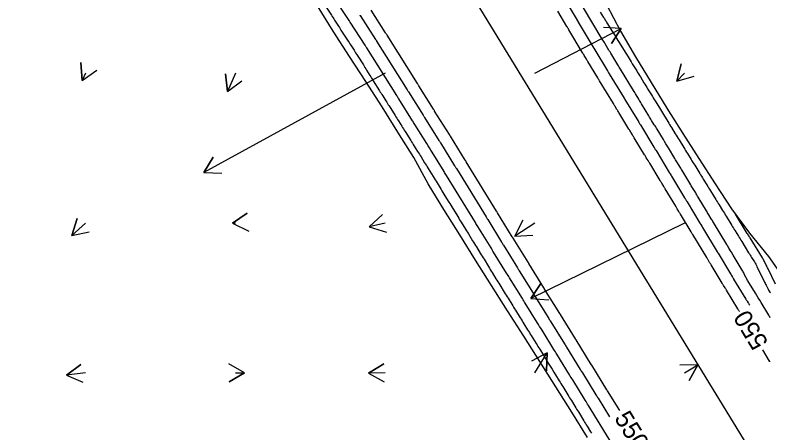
# Model space of a CAD drawing. Extents: x 954385 to 988206, y 1868364 to 1924553.
# Drawn here: x 956633.6 to 956885.7, y 1921348.9 to 1921488.4 of the extents above; entities that cross this region are included whole.
import ezdxf

# ---------------------------------------------------------------- set-up
doc = ezdxf.new("R2010")
doc.units = 0
for name, color, linetype in [('24', 7, 'Continuous'), ('26', 7, 'Continuous'), ('5', 7, 'Continuous'), ('6', 7, 'Continuous'), ('7', 7, 'Continuous'), ('Default', 7, 'Continuous')]:
    doc.layers.add(name, color=color, linetype=linetype)

msp = doc.modelspace()

# ---------------------------------------------------------------- linework, layer by layer
at = {"layer": '24'}
for points in [[(956824.81, 1921347.37), (956819.48, 1921355.83), (956814.15, 1921364.29), (956808.81, 1921372.75), (956803.45, 1921381.19), (956798.08, 1921389.63), (956792.73, 1921398.08), (956787.39, 1921406.53), (956782.08, 1921415.01), (956776.8, 1921423.5), (956771.5, 1921431.98), (956766.73, 1921440.79), (956761.4, 1921449.25), (956756.18, 1921457.78), (956750.7, 1921466.15), (956745.31, 1921474.58), (956739.85, 1921482.96), (956734.55, 1921491.44)], [(956831.07, 1921491.88), (956835.81, 1921483.05), (956840.83, 1921474.4), (956846.08, 1921465.89), (956851.23, 1921457.32), (956856.61, 1921448.89), (956861.99, 1921440.46), (956867.43, 1921432.06), (956872.87, 1921423.67), (956878.85, 1921415.6), (956885.2, 1921407.77), (956890.96, 1921399.57)]]:
    msp.add_lwpolyline(points, dxfattribs=at)
at = {"layer": '26'}
for points in [[(956807.13, 1921468.93), (956836.05, 1921483.93), (956832.82, 1921478.87), (956836.05, 1921483.93), (956830.06, 1921484.2)], [(956657.13, 1921468.93), (956656, 1921466.52), (956655.5, 1921472.5), (956656, 1921466.52), (956660.92, 1921469.95)], [(956857.13, 1921468.93), (956854.6, 1921466.31), (956856.05, 1921472.13), (956854.6, 1921466.31), (956860.36, 1921467.96)], [(956757.13, 1921468.93), (956696.62, 1921435.77), (956699.73, 1921440.9), (956696.62, 1921435.77), (956702.61, 1921435.64)], [(956707.13, 1921468.93), (956704.51, 1921462.81), (956703.8, 1921468.76), (956704.51, 1921462.81), (956709.31, 1921466.4)], [(956657.13, 1921418.93), (956652.49, 1921414.76), (956654.35, 1921420.46), (956652.49, 1921414.76), (956658.36, 1921416)], [(956707.13, 1921418.93), (956706.18, 1921418.85), (956711.12, 1921422.26), (956706.18, 1921418.85), (956711.59, 1921416.27)], [(956757.13, 1921418.93), (956751.85, 1921417.72), (956756.24, 1921421.8), (956751.85, 1921417.72), (956757.58, 1921415.95)], [(956807.13, 1921418.93), (956800.46, 1921414.56), (956803.16, 1921419.92), (956800.46, 1921414.56), (956806.45, 1921414.9)], [(956857.13, 1921418.93), (956805.87, 1921393.76), (956809.22, 1921398.74), (956805.87, 1921393.76), (956811.86, 1921393.36)], [(956807.13, 1921368.93), (956811.33, 1921375.6), (956811.1, 1921369.6), (956811.33, 1921375.6), (956806.02, 1921372.8)], [(956657.13, 1921368.93), (956650.7, 1921368.15), (956655.5, 1921371.75), (956650.7, 1921368.15), (956656.22, 1921365.8)], [(956707.13, 1921368.93), (956710.18, 1921368.98), (956705.04, 1921365.89), (956710.18, 1921368.98), (956704.94, 1921371.89)], [(956757.13, 1921368.93), (956751.58, 1921368.84), (956756.73, 1921371.92), (956751.58, 1921368.84), (956756.83, 1921365.92)], [(956857.13, 1921368.93), (956861.65, 1921371.57), (956858.68, 1921366.36), (956861.65, 1921371.57), (956855.65, 1921371.54)]]:
    msp.add_lwpolyline(points, dxfattribs=at)
at = {"layer": '6'}
for points in [[(956835.53, 1921356.32), (956831.44, 1921362.96), (956831.36, 1921363.1), (956831.27, 1921363.23), (956826.2, 1921371.47), (956826.15, 1921371.54), (956826.11, 1921371.61), (956826.07, 1921371.68), (956826.02, 1921371.75), (956820.95, 1921379.96), (956820.9, 1921380.03), (956820.85, 1921380.11), (956820.8, 1921380.19), (956820.75, 1921380.27), (956815.69, 1921388.44), (956815.64, 1921388.53), (956815.59, 1921388.62), (956815.53, 1921388.71), (956815.48, 1921388.79), (956810.43, 1921396.91), (956810.37, 1921397.01), (956810.31, 1921397.11), (956810.25, 1921397.21), (956810.19, 1921397.31), (956805.18, 1921405.4), (956805.11, 1921405.5), (956805.04, 1921405.61), (956804.98, 1921405.72), (956804.91, 1921405.83), (956799.94, 1921413.89), (956799.87, 1921414.01), (956799.8, 1921414.13), (956799.72, 1921414.24), (956799.65, 1921414.36), (956794.7, 1921422.4), (956794.63, 1921422.52), (956794.56, 1921422.64), (956794.48, 1921422.76), (956794.41, 1921422.88), (956784.24, 1921439.43), (956784.16, 1921439.55), (956784.08, 1921439.68), (956784, 1921439.81), (956783.93, 1921439.94), (956778.99, 1921447.92), (956778.91, 1921448.05), (956778.83, 1921448.19), (956778.74, 1921448.32), (956778.66, 1921448.46), (956773.7, 1921456.35), (956773.6, 1921456.51), (956773.51, 1921456.66), (956773.41, 1921456.81), (956773.32, 1921456.96), (956768.41, 1921464.79), (956768.3, 1921464.96), (956768.19, 1921465.13), (956768.09, 1921465.3), (956767.98, 1921465.48), (956757.82, 1921481.64), (956757.69, 1921481.86), (956757.56, 1921482.07), (956757.42, 1921482.28), (956757.28, 1921482.49), (956752.45, 1921489.97)], [(956875.51, 1921389.39), (956875.41, 1921389.55), (956875.3, 1921389.73), (956875.19, 1921389.91), (956875.07, 1921390.1), (956874.96, 1921390.28), (956871.15, 1921396.56), (956871.04, 1921396.75), (956870.92, 1921396.94), (956870.8, 1921397.13), (956870.69, 1921397.32), (956870.23, 1921398.08), (956870.11, 1921398.27), (956869.99, 1921398.46), (956869.88, 1921398.65), (956869.76, 1921398.84), (956866.02, 1921405.03), (956865.9, 1921405.23), (956865.78, 1921405.43), (956865.66, 1921405.62), (956865.54, 1921405.82), (956865.06, 1921406.62), (956864.94, 1921406.82), (956864.82, 1921407.02), (956864.7, 1921407.21), (956864.57, 1921407.41), (956859.89, 1921415.16), (956859.77, 1921415.36), (956859.64, 1921415.57), (956859.52, 1921415.78), (956859.39, 1921415.99), (956855.8, 1921421.94), (956855.67, 1921422.16), (956855.54, 1921422.38), (956855.4, 1921422.6), (956855.27, 1921422.82), (956854.74, 1921423.7), (956854.61, 1921423.92), (956854.48, 1921424.14), (956854.34, 1921424.36), (956854.21, 1921424.58), (956850.7, 1921430.4), (956850.56, 1921430.63), (956850.42, 1921430.86), (956850.28, 1921431.09), (956850.14, 1921431.32), (956849.58, 1921432.24), (956849.44, 1921432.47), (956849.3, 1921432.7), (956849.17, 1921432.93), (956849.03, 1921433.15), (956845.55, 1921438.88), (956845.41, 1921439.11), (956845.27, 1921439.35), (956845.12, 1921439.59), (956844.98, 1921439.82), (956844.4, 1921440.77), (956844.26, 1921441.01), (956844.12, 1921441.24), (956843.97, 1921441.48), (956843.83, 1921441.72), (956840.39, 1921447.37), (956840.24, 1921447.61), (956840.1, 1921447.85), (956839.95, 1921448.09), (956839.8, 1921448.34), (956839.21, 1921449.3), (956839.07, 1921449.55), (956838.92, 1921449.79), (956838.77, 1921450.03), (956838.62, 1921450.27), (956835.21, 1921455.87), (956835.06, 1921456.12), (956834.91, 1921456.36), (956834.76, 1921456.61), (956834.61, 1921456.86), (956834.02, 1921457.84), (956833.87, 1921458.08), (956833.72, 1921458.33), (956833.57, 1921458.57), (956833.42, 1921458.82), (956828.82, 1921466.37), (956828.67, 1921466.62), (956828.52, 1921466.87), (956828.36, 1921467.12), (956828.21, 1921467.37), (956824.89, 1921472.86), (956824.73, 1921473.11), (956824.58, 1921473.37), (956824.42, 1921473.63), (956824.26, 1921473.88), (956823.64, 1921474.91), (956823.49, 1921475.16), (956823.33, 1921475.42), (956823.18, 1921475.68), (956823.02, 1921475.94), (956818.54, 1921483.46), (956818.38, 1921483.74), (956818.21, 1921484.01), (956818.05, 1921484.29), (956817.88, 1921484.56), (956814.85, 1921489.64)], [(956885.69, 1921372.64), (956885.61, 1921372.78), (956885.58, 1921372.83), (956885.55, 1921372.87), (956883.3, 1921376.57)]]:
    msp.add_lwpolyline(points, dxfattribs=at)
at = {"layer": '7'}
for points in [[(956811.4, 1921503.25), (956821.3, 1921486.65), (956821.36, 1921486.54), (956821.43, 1921486.43), (956821.59, 1921486.15), (956821.66, 1921486.04), (956821.69, 1921485.99), (956826.65, 1921477.66), (956826.7, 1921477.58), (956826.74, 1921477.51), (956826.79, 1921477.43), (956826.83, 1921477.36), (956831.42, 1921469.79), (956831.52, 1921469.63), (956831.62, 1921469.46), (956831.83, 1921469.12), (956831.88, 1921469.04), (956831.93, 1921468.96), (956831.98, 1921468.87), (956832.03, 1921468.79), (956837.02, 1921460.59), (956837.08, 1921460.5), (956837.13, 1921460.42), (956837.18, 1921460.33), (956837.24, 1921460.24), (956841.77, 1921452.79), (956841.82, 1921452.7), (956841.88, 1921452.61), (956841.94, 1921452.52), (956841.99, 1921452.43), (956842.27, 1921451.97), (956842.44, 1921451.69), (956846.95, 1921444.29), (956847.01, 1921444.19), (956847.07, 1921444.1), (956847.12, 1921444), (956847.18, 1921443.91), (956847.41, 1921443.52), (956847.47, 1921443.43), (956847.53, 1921443.33), (956847.59, 1921443.24), (956847.65, 1921443.14), (956852.09, 1921435.81), (956852.15, 1921435.71), (956852.22, 1921435.6), (956852.28, 1921435.5), (956852.34, 1921435.4), (956852.59, 1921434.99), (956852.65, 1921434.89), (956852.72, 1921434.78), (956852.78, 1921434.68), (956852.84, 1921434.58), (956857.21, 1921427.35), (956857.28, 1921427.23), (956857.35, 1921427.12), (956857.42, 1921427.01), (956857.48, 1921426.9), (956857.75, 1921426.45), (956857.82, 1921426.34), (956857.89, 1921426.23), (956857.96, 1921426.11), (956858.03, 1921426), (956862.3, 1921418.9), (956862.38, 1921418.78), (956862.45, 1921418.65), (956862.53, 1921418.53), (956862.6, 1921418.41), (956862.9, 1921417.91), (956862.98, 1921417.78), (956863.05, 1921417.66), (956863.13, 1921417.54), (956863.2, 1921417.41), (956868.06, 1921409.37), (956868.15, 1921409.24), (956868.23, 1921409.1), (956868.31, 1921408.97), (956868.39, 1921408.84), (956872.54, 1921401.97), (956872.71, 1921401.69), (956872.89, 1921401.4), (956873.23, 1921400.83), (956873.32, 1921400.69), (956873.4, 1921400.55), (956873.49, 1921400.41), (956873.58, 1921400.26), (956877.7, 1921393.48), (956877.79, 1921393.34), (956877.88, 1921393.19), (956877.97, 1921393.04), (956878.06, 1921392.89), (956878.42, 1921392.3), (956878.51, 1921392.15), (956878.6, 1921392), (956878.69, 1921391.85), (956878.78, 1921391.71), (956878.93, 1921391.47)], [(956835, 1921341.92), (956825.07, 1921358.05), (956824.8, 1921358.48), (956824.53, 1921358.92), (956824.26, 1921359.36), (956823.99, 1921359.79), (956819.81, 1921366.58), (956819.55, 1921367.01), (956819.29, 1921367.43), (956819.02, 1921367.86), (956818.76, 1921368.29), (956814.53, 1921375.13), (956814.28, 1921375.53), (956814.03, 1921375.94), (956813.77, 1921376.35), (956813.52, 1921376.75), (956809.57, 1921383.13), (956809.17, 1921383.79), (956808.76, 1921384.44), (956808.35, 1921385.1), (956807.95, 1921385.75), (956803.97, 1921392.17), (956803.73, 1921392.55), (956803.49, 1921392.94), (956803.25, 1921393.33), (956803.01, 1921393.71), (956798.68, 1921400.7), (956798.45, 1921401.07), (956798.22, 1921401.44), (956797.99, 1921401.81), (956797.76, 1921402.18), (956793.41, 1921409.23), (956793.19, 1921409.59), (956792.97, 1921409.95), (956792.75, 1921410.31), (956792.53, 1921410.67), (956788.17, 1921417.76), (956787.95, 1921418.12), (956787.73, 1921418.47), (956787.51, 1921418.82), (956787.3, 1921419.17), (956777.67, 1921434.83), (956777.47, 1921435.17), (956777.26, 1921435.51), (956777.05, 1921435.84), (956776.84, 1921436.18), (956772.9, 1921442.56), (956772.45, 1921443.29), (956772, 1921444.01), (956771.55, 1921444.74), (956771.09, 1921445.46), (956767.07, 1921451.88), (956766.87, 1921452.18), (956766.68, 1921452.48), (956766.49, 1921452.79), (956766.3, 1921453.09), (956761.71, 1921460.41), (956761.54, 1921460.68), (956761.37, 1921460.96), (956761.2, 1921461.23), (956761.03, 1921461.5), (956751, 1921477.47), (956750.87, 1921477.68), (956750.73, 1921477.89), (956750.6, 1921478.1), (956750.46, 1921478.31), (956745.49, 1921486), (956745.4, 1921486.15), (956745.3, 1921486.29), (956745.21, 1921486.44), (956745.11, 1921486.59), (956739.97, 1921494.54)], [(956737.28, 1921491.33), (956739.23, 1921488.31), (956739.5, 1921487.9), (956739.77, 1921487.49), (956740.03, 1921487.08), (956740.3, 1921486.67), (956741.36, 1921485.03), (956741.63, 1921484.62), (956741.89, 1921484.21), (956742.16, 1921483.8), (956742.42, 1921483.39), (956744.58, 1921480.05), (956744.85, 1921479.62), (956745.13, 1921479.2), (956745.4, 1921478.78), (956745.68, 1921478.35), (956746.77, 1921476.66), (956747.05, 1921476.23), (956747.32, 1921475.81), (956747.59, 1921475.38), (956747.86, 1921474.95), (956749.89, 1921471.71), (956750.17, 1921471.27), (956750.44, 1921470.83), (956750.72, 1921470.4), (956750.99, 1921469.96), (956752.09, 1921468.21), (956752.36, 1921467.77), (956752.64, 1921467.34), (956752.91, 1921466.9), (956753.19, 1921466.46), (956755.29, 1921463.12), (956755.55, 1921462.69), (956755.82, 1921462.27), (956756.09, 1921461.84), (956756.36, 1921461.42), (956757.42, 1921459.72), (956757.69, 1921459.29), (956757.96, 1921458.87), (956758.22, 1921458.44), (956758.49, 1921458.02), (956760.47, 1921454.87), (956760.75, 1921454.42), (956761.03, 1921453.98), (956761.31, 1921453.53), (956761.59, 1921453.08), (956762.71, 1921451.29), (956762.99, 1921450.84), (956763.27, 1921450.4), (956763.55, 1921449.95), (956763.83, 1921449.5), (956765.73, 1921446.49), (956766.01, 1921446.03), (956766.3, 1921445.58), (956766.58, 1921445.12), (956766.87, 1921444.66), (956768.02, 1921442.84), (956768.3, 1921442.38), (956768.59, 1921441.93), (956768.87, 1921441.47), (956769.16, 1921441.01), (956770.34, 1921439.09), (956770.64, 1921438.61), (956770.93, 1921438.14), (956771.22, 1921437.67), (956771.51, 1921437.19), (956773.18, 1921434.49), (956773.52, 1921433.95), (956773.85, 1921433.42), (956774.18, 1921432.88), (956774.51, 1921432.35), (956775.84, 1921430.18), (956776.16, 1921429.65), (956776.49, 1921429.12), (956776.81, 1921428.6), (956777.13, 1921428.07), (956778.43, 1921425.96), (956778.76, 1921425.43), (956779.08, 1921424.9), (956779.41, 1921424.37), (956779.73, 1921423.84), (956781.1, 1921421.63), (956781.42, 1921421.1), (956781.74, 1921420.58), (956782.06, 1921420.05), (956782.39, 1921419.53), (956783.68, 1921417.43), (956784, 1921416.91), (956784.32, 1921416.38), (956784.64, 1921415.86), (956784.97, 1921415.33), (956786.37, 1921413.04), (956786.69, 1921412.53), (956787.01, 1921412.01), (956787.33, 1921411.49), (956787.65, 1921410.97), (956788.92, 1921408.9), (956789.24, 1921408.38), (956789.56, 1921407.86), (956789.88, 1921407.34), (956790.2, 1921406.83), (956791.67, 1921404.44), (956791.98, 1921403.93), (956792.3, 1921403.42), (956792.61, 1921402.92), (956792.93, 1921402.41), (956794.18, 1921400.37), (956794.5, 1921399.86), (956794.81, 1921399.35), (956795.12, 1921398.84), (956795.44, 1921398.34), (956796.98, 1921395.86), (956797.29, 1921395.36), (956797.6, 1921394.86), (956797.91, 1921394.35), (956798.22, 1921393.85), (956799.46, 1921391.85), (956799.77, 1921391.35), (956800.08, 1921390.85), (956800.39, 1921390.35), (956800.7, 1921389.85), (956802.29, 1921387.29), (956802.59, 1921386.8), (956802.9, 1921386.3), (956803.21, 1921385.81), (956803.51, 1921385.31), (956804.74, 1921383.34), (956805.04, 1921382.85), (956805.35, 1921382.35), (956805.66, 1921381.86), (956805.96, 1921381.37), (956807.6, 1921378.72), (956807.9, 1921378.24), (956808.2, 1921377.75), (956808.5, 1921377.26), (956808.8, 1921376.78), (956810.01, 1921374.83), (956810.31, 1921374.34), (956810.61, 1921373.85), (956810.91, 1921373.36), (956811.22, 1921372.88), (956812.91, 1921370.14), (956813.5, 1921369.18), (956814.09, 1921368.22), (956815.28, 1921366.31), (956815.58, 1921365.83), (956815.87, 1921365.35), (956816.17, 1921364.87), (956816.47, 1921364.39), (956818.21, 1921361.55), (956818.5, 1921361.08), (956818.79, 1921360.61), (956819.08, 1921360.14), (956819.37, 1921359.66), (956820.54, 1921357.78), (956820.83, 1921357.3), (956821.12, 1921356.83), (956821.41, 1921356.36), (956821.7, 1921355.89), (956823.52, 1921352.93), (956823.81, 1921352.47), (956824.09, 1921352.01), (956824.37, 1921351.55), (956824.66, 1921351.09), (956825.79, 1921349.24), (956826.08, 1921348.78)], [(956885.82, 1921387.34), (956885.66, 1921387.61), (956885.49, 1921387.89), (956885.32, 1921388.16), (956882.75, 1921392.4), (956882.27, 1921393.18), (956881.79, 1921393.96), (956881.32, 1921394.74), (956880.84, 1921395.52), (956878.34, 1921399.63), (956878.17, 1921399.92), (956878.01, 1921400.21), (956877.85, 1921400.51), (956877.7, 1921400.81), (956877.11, 1921402.03), (956876.96, 1921402.33), (956876.8, 1921402.63), (956876.64, 1921402.92), (956876.47, 1921403.21), (956873.46, 1921408.18), (956873.28, 1921408.48), (956873.1, 1921408.78), (956872.92, 1921409.08), (956872.73, 1921409.38), (956872, 1921410.59), (956871.82, 1921410.89), (956871.64, 1921411.19), (956871.46, 1921411.49), (956871.27, 1921411.79), (956866.86, 1921419.1), (956866.66, 1921419.42), (956866.46, 1921419.75), (956866.27, 1921420.07), (956866.07, 1921420.4), (956865.29, 1921421.7), (956865.09, 1921422.03), (956864.89, 1921422.35), (956864.7, 1921422.68), (956864.5, 1921423.01), (956861.71, 1921427.63), (956861.51, 1921427.97), (956861.3, 1921428.31), (956861.09, 1921428.65), (956860.89, 1921429), (956860.06, 1921430.37), (956859.85, 1921430.71), (956859.64, 1921431.05), (956859.44, 1921431.39), (956859.23, 1921431.74), (956856.56, 1921436.16), (956856.34, 1921436.51), (956856.13, 1921436.87), (956855.91, 1921437.23), (956855.7, 1921437.58), (956854.83, 1921439.01), (956854.61, 1921439.37), (956854.4, 1921439.72), (956854.18, 1921440.08), (956853.97, 1921440.44), (956851.79, 1921444.02), (956851.37, 1921444.72), (956850.94, 1921445.42), (956850.52, 1921446.12), (956850.09, 1921446.82), (956847.98, 1921450.29), (956847.76, 1921450.66), (956847.53, 1921451.02), (956847.31, 1921451.39), (956847.08, 1921451.76), (956846.19, 1921453.23), (956845.97, 1921453.59), (956845.74, 1921453.96), (956845.52, 1921454.33), (956845.29, 1921454.7), (956842.81, 1921458.77), (956842.58, 1921459.15), (956842.36, 1921459.52), (956842.13, 1921459.89), (956841.9, 1921460.27), (956840.99, 1921461.76), (956840.77, 1921462.13), (956840.54, 1921462.5), (956840.31, 1921462.88), (956840.09, 1921463.25), (956835.8, 1921470.29), (956835.57, 1921470.66), (956835.34, 1921471.04), (956835.11, 1921471.42), (956834.88, 1921471.8), (956832.51, 1921475.7), (956832.28, 1921476.09), (956832.04, 1921476.48), (956831.81, 1921476.87), (956831.57, 1921477.26), (956830.63, 1921478.82), (956830.39, 1921479.21), (956830.16, 1921479.6), (956829.92, 1921479.99), (956829.69, 1921480.38), (956823.46, 1921490.83)], [(956748.71, 1921488.38), (956748.77, 1921488.29), (956748.83, 1921488.21), (956753.98, 1921480.24), (956754.06, 1921480.11), (956754.14, 1921479.98), (956754.23, 1921479.85), (956754.31, 1921479.72), (956764.56, 1921463.39), (956764.67, 1921463.22), (956764.78, 1921463.04), (956764.89, 1921462.87), (956765, 1921462.7), (956769.85, 1921454.96), (956769.97, 1921454.76), (956770.1, 1921454.57), (956770.22, 1921454.38), (956770.34, 1921454.18), (956775.15, 1921446.53), (956775.28, 1921446.32), (956775.41, 1921446.1), (956775.55, 1921445.89), (956775.68, 1921445.67), (956780.39, 1921438.04), (956780.53, 1921437.82), (956780.67, 1921437.59), (956780.81, 1921437.37), (956780.95, 1921437.15), (956790.86, 1921421.02), (956791, 1921420.79), (956791.14, 1921420.56), (956791.29, 1921420.32), (956791.43, 1921420.09), (956796.09, 1921412.51), (956796.24, 1921412.28), (956796.38, 1921412.04), (956796.53, 1921411.8), (956796.67, 1921411.56), (956801.33, 1921404.01), (956801.48, 1921403.77), (956801.63, 1921403.53), (956801.78, 1921403.28), (956801.93, 1921403.04), (956806.59, 1921395.53), (956806.74, 1921395.28), (956806.9, 1921395.03), (956807.06, 1921394.78), (956807.21, 1921394.52), (956811.85, 1921387.05), (956812.01, 1921386.79), (956812.17, 1921386.53), (956812.34, 1921386.27), (956812.5, 1921386.01), (956817.1, 1921378.57), (956817.27, 1921378.3), (956817.44, 1921378.03), (956817.61, 1921377.75), (956817.77, 1921377.48), (956822.35, 1921370.08), (956822.52, 1921369.8), (956822.7, 1921369.52), (956822.87, 1921369.24), (956823.04, 1921368.96), (956827.59, 1921361.58), (956827.77, 1921361.3), (956827.94, 1921361.01), (956828.12, 1921360.72), (956828.3, 1921360.43), (956832.12, 1921354.22)], [(956829.03, 1921489.4), (956830.14, 1921487.62), (956830.42, 1921487.18), (956830.69, 1921486.73), (956830.97, 1921486.29), (956831.25, 1921485.84), (956833.16, 1921482.78), (956833.46, 1921482.29), (956833.77, 1921481.8), (956834.07, 1921481.32), (956834.37, 1921480.83), (956835.88, 1921478.38), (956836.79, 1921476.9), (956838.31, 1921474.43), (956838.66, 1921473.86), (956839.01, 1921473.29), (956839.36, 1921472.72), (956839.71, 1921472.15), (956841.19, 1921469.74), (956841.5, 1921469.24), (956841.8, 1921468.74), (956842.11, 1921468.25), (956842.41, 1921467.75), (956843.63, 1921465.76), (956843.94, 1921465.27), (956844.24, 1921464.77), (956844.55, 1921464.27), (956844.85, 1921463.78), (956846.11, 1921461.73), (956846.42, 1921461.22), (956846.73, 1921460.72), (956847.04, 1921460.21), (956847.35, 1921459.7), (956848.8, 1921457.36), (956849.14, 1921456.8), (956849.48, 1921456.25), (956849.82, 1921455.69), (956850.16, 1921455.14), (956851.57, 1921452.84), (956851.89, 1921452.33), (956852.2, 1921451.82), (956852.51, 1921451.3), (956852.83, 1921450.79), (956854.08, 1921448.75), (956854.4, 1921448.24), (956854.71, 1921447.73), (956855.03, 1921447.22), (956855.34, 1921446.7), (956856.92, 1921444.14), (956857.22, 1921443.64), (956857.53, 1921443.15), (956857.83, 1921442.66), (956858.13, 1921442.17), (956859.35, 1921440.2), (956859.65, 1921439.7), (956859.95, 1921439.21), (956860.26, 1921438.72), (956860.56, 1921438.23), (956862.25, 1921435.5), (956862.54, 1921435.02), (956862.84, 1921434.54), (956863.13, 1921434.06), (956863.43, 1921433.58), (956864.62, 1921431.66), (956864.91, 1921431.18), (956865.21, 1921430.7), (956865.51, 1921430.22), (956865.8, 1921429.74), (956867.6, 1921426.83), (956867.89, 1921426.37), (956868.18, 1921425.91), (956868.46, 1921425.44), (956868.75, 1921424.98), (956869.9, 1921423.13), (956870.18, 1921422.66), (956870.47, 1921422.2), (956870.76, 1921421.73), (956871.04, 1921421.27), (956872.96, 1921418.17), (956873.23, 1921417.72), (956873.51, 1921417.28), (956873.79, 1921416.83), (956874.06, 1921416.38), (956875.17, 1921414.59), (956875.45, 1921414.14), (956875.72, 1921413.69), (956876, 1921413.24), (956876.28, 1921412.79), (956878.59, 1921409.04), (956878.83, 1921408.65), (956879.07, 1921408.27), (956879.31, 1921407.88), (956879.54, 1921407.49), (956880.5, 1921405.95), (956880.73, 1921405.56), (956880.95, 1921405.17), (956881.17, 1921404.77), (956881.37, 1921404.36), (956883.75, 1921399.56), (956883.92, 1921399.22), (956884.09, 1921398.88), (956884.26, 1921398.55), (956884.42, 1921398.21), (956885.09, 1921396.86), (956885.27, 1921396.53), (956885.47, 1921396.21), (956885.68, 1921395.9), (956885.92, 1921395.61)], [(956887.57, 1921398.59), (956885.07, 1921403.64), (956884.92, 1921403.95), (956884.76, 1921404.26), (956884.61, 1921404.57), (956884.45, 1921404.88), (956883.84, 1921406.12), (956883.68, 1921406.43), (956883.52, 1921406.74), (956883.35, 1921407.04), (956883.17, 1921407.33), (956879.04, 1921414.02), (956878.89, 1921414.27), (956878.74, 1921414.52), (956878.43, 1921415.01), (956878.36, 1921415.13), (956878.28, 1921415.26), (956878.21, 1921415.38), (956878.13, 1921415.5), (956874.16, 1921421.93)]]:
    msp.add_lwpolyline(points, dxfattribs=at)
at = {"layer": 'Default'}
msp.add_line((957221.14, 1920784.24), (956045.8, 1922705.18), dxfattribs=at)

# ---------------------------------------------------------------- texts
at = {"layer": '5'}
for rotation, p in [(121.2999, (956885.31, 1921379.05)), (301.5643, (956833.53, 1921353.83))]:
    msp.add_text('550', height=6, rotation=rotation, dxfattribs=at).set_placement(p)

doc.saveas('drawing.dxf')
